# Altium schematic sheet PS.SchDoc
size A4
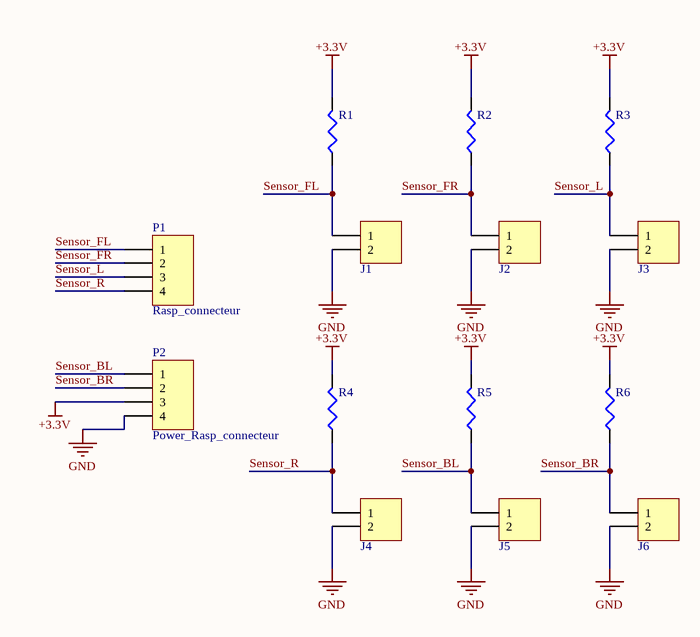
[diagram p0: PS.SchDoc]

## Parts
J1  Connecteur 2  [Header_2Ecam]  (value not drawn)
J2  Connecteur 2  [Header_2Ecam]  (value not drawn)
J3  Connecteur 2  [Header_2Ecam]  (value not drawn)
J4  Connecteur 2  [Header_2Ecam]  (value not drawn)
J5  Connecteur 2  [Header_2Ecam]  (value not drawn)
J6  Connecteur 2  [Header_2Ecam]  (value not drawn)
P1  Rasp_connecteur  [Header4_ecam]
P2  Power_Rasp_connecteur  [Header4_ecam]
R1  Résistance  [AXIAL-0.3]  (value not drawn)
R2  Résistance  [AXIAL-0.3]  (value not drawn)
R3  Résistance  [AXIAL-0.3]  (value not drawn)
R4  Résistance  [AXIAL-0.3]  (value not drawn)
R5  Résistance  [AXIAL-0.3]  (value not drawn)
R6  Résistance  [AXIAL-0.3]  (value not drawn)

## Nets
+3.3V: P2.3 R1.2 R2.2 R3.2 R4.2 R5.2 R6.2
GND: J1.2 J2.2 J3.2 J4.2 J5.2 J6.2 P2.4
Sensor_BL: J5.1 P2.1 R5.1
Sensor_BR: J6.1 P2.2 R6.1
Sensor_FL: J1.1 P1.1 R1.1
Sensor_FR: J2.1 P1.2 R2.1
Sensor_L: J3.1 P1.3 R3.1
Sensor_R: J4.1 P1.4 R4.1

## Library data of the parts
J1-J6 = Connecteur 2: Connecteur
P1 P2 = Header 4: Header, 4-Pin
R1-R6 = Résistance: Résistance standard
